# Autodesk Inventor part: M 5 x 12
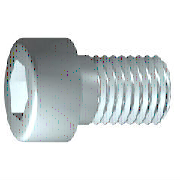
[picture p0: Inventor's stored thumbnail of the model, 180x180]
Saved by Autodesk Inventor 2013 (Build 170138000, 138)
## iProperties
IsCustomPart: 0
Created: 2009-02
Part Number: M 5 x 12
Material: 강, 연강
Description: 6각머리 태핑 나사
Document SubType Name: Modeling
Standard: KS B 1003
Designer: KYOUNG IL JANG
Standards Organization: KS
Language: ko-KR
Size Designation: M 5 x 12
Categories: <MemberInstance><Categories><Category DisplayName="조임쇠" InternalName="e4da775c-781d-43d5-af7c-5136215cf5a6" Mnemonic="FSTN"><Category DisplayName="볼트" InternalN
Density: 7.86 g/cm^3
Mass: 3.72825 g
Surface Area: 4.62573 cm^2
Volume: 0.474332 cm^3
Author: KYOUNG IL JANG
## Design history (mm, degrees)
sketch "스케치1"
  geometry: L1 (-1.167, 0)-(12, 0); L2 (12, 0)-(12, 2.5); L3 (12, 2.5)-(2, 2.5); L4 (2, 2.5)-(1.509, 2.5); L5 (1.509, 2.5)-(0, 2.5); L6 (0, 2.5)-(0, 4.25); L7 (0, 4.25)-(-5, 4.25); L8 (-5, 4.25)-(-5, 2.309); L9 (-5, 2.309)-(-2.5, 2.309); L10 (-2.5, 2.309)-(-1.167, 0); L11 (-8.4, 0)-(15.4, 0) reference; L12 (0, -0.85)-(0, 5.1) reference; L13 (2, 2.5)-(0, 2.5)
  constraints: 22 end point, 6 parallel, 2 collinear, 2 perpendicular, 1 horizontal, 1 point on line
  dimensions: "d1" = 10 distance from line of L3.end L2 (= GEL); "d2" = 0.49086 distance of L4.end L3.end (computed from GAL); "d3" = 5 distance between parallel lines of L8 L6 (= KOH); "d4" = 2.5 distance of L8.end L9.end (= INTI); "d5" = 60 deg angle of L10 L1; "d6" = 5 diameter of L3 L1 (= GD); "d7" = 5 diameter of L5 L1 (= BDM); "d8" = 4.6188 diameter of L9 L1 (= 1.1547 x SW); "d9" = 8.5 diameter of L7 L1 (= KOD); "d26" = 12 distance between parallel lines of L12 L2 (= NLG)
revolve "본체" sketch "스케치1" stored, may be unused: angle "d10" = 90 deg
sketch "스케치2"
  geometry: L1 (0, -5.95)-(0, 5.95) reference; L2 (-5.95, 0)-(5.95, 0) reference; L3 (2.309, 0)-(1.155, -2); L4 (1.155, -2)-(-1.155, -2); L5 (-1.155, -2)-(-2.309, 0); L6 (-2.309, 0)-(-1.155, 2); L7 (-1.155, 2)-(1.155, 2); L8 (1.155, 2)-(2.309, 0); 2 further points
  constraints: 12 end point, 1 coincident, 1 horizontal alignment, 1 point on line, 12 other
extrude "슬롯" join sketch "스케치2" stored distance "d11" = 10; taper "d12" = 0 deg
workplane "Work Plane1"
fillet "Fillet2" dims "d30" = 0.1 (= R)
body "Solid1"
fillet "모깎기1" dims "d17" = 0.5 (= RR)
feature "스레드" dims "d13" = 10 (= GEL), "d14" = 0
chamfer "모따기1" distance "d15" = 0.49076 (= -0.5 x SPD + 0.5 x GD); stored, may be unused: second distance "d16" = 0.49076 (= GUL), angle "d27" = 45 deg
other parameters: "GD" = 5 (= NND) [user parameter; used in 2 equation terms], "NLG" = 12 [user parameter; used in 1 equation term], "GEL" = 10 [user parameter; used in 2 equation terms], "KOD" = 8.5 [user parameter; used in 1 equation term], "KOH" = 5 [user parameter; used in 1 equation term], "INTI" = 2.5 [user parameter; used in 1 equation term], "GAL" = 0.49076 (= 0.61345 x PTC) [user parameter; used in 1 equation term], "GUL" = 0.49076 (= 0.61345 x PTC) [user parameter; used in 1 equation term], "BDM" = 5 (= NND) [user parameter; used in 1 equation term], "SW" = 4 [user parameter; used in 2 equation terms], "RR" = 0.5 [user parameter; used in 1 equation term], "SPD" = 4.01848 (= NND - 1.2269 x PTC) [user parameter; used in 1 equation term], "d19" = 0, "d28" = 0, "d29" = 0, "R" = 0.1 [user parameter; used in 1 equation term], "PHH" = 0.2 [user parameter], "GD1" = 4.01848 (= THREADDIA - 1.2269 x PTC) [user parameter], "THREADDIA" = 5 [user parameter; used in 1 equation term], "FAWI" = 45 deg [user parameter], "TPU" = 12.5 (computed from PTC) [user parameter], "PTC" = 0.8 [user parameter; used in 5 equation terms], "NND" = 5 [user parameter; used in 3 equation terms], "TOA" = 30 deg [user parameter], "E0" = 4.62 (= 1.155 x SW) [user parameter]
